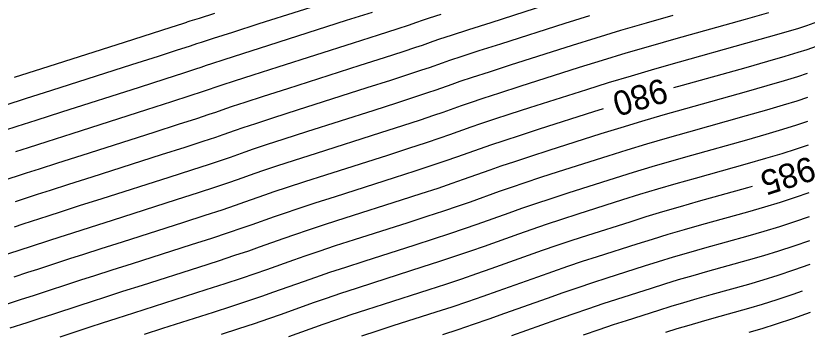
# Model space of a CAD drawing. Extents: x 2175772 to 2185556, y 721391 to 722853.
# Drawn here: x 2178980.9 to 2179071.3, y 721931.4 to 721967.6 of the extents above; entities that cross this region are included whole.
import ezdxf

# ---------------------------------------------------------------- set-up
doc = ezdxf.new("R2010")
doc.units = 0
doc.layers.add('DT_X_Contour_Major', color=7, linetype='Continuous')
doc.layers.add('DT_X_Contour_Minor', color=7, linetype='Continuous')

msp = doc.modelspace()

# ---------------------------------------------------------------- linework, layer by layer
at = {"layer": 'DT_X_Contour_Major'}
for points in [[(2178980.023, 721948.963), (2178981.318, 721949.388), (2178982.129, 721949.65), (2178983.591, 721950.121), (2178985.704, 721950.798), (2178988.467, 721951.683), (2178996.705, 721954.318), (2178999.462, 721955.202), (2179001.555, 721955.878), (2179002.983, 721956.345), (2179003.746, 721956.603), (2179004.897, 721957.015), (2179005.662, 721957.274), (2179007.096, 721957.743), (2179009.198, 721958.421), (2179011.969, 721959.309), (2179020.249, 721961.956), (2179023.022, 721962.845), (2179025.132, 721963.526), (2179026.578, 721964), (2179027.362, 721964.265), (2179028.566, 721964.696), (2179029.32, 721964.952), (2179030.678, 721965.397), (2179032.64, 721966.03), (2179035.206, 721966.852), (2179042.853, 721969.296)], [(2179056.073, 721959.398), (2179057.065, 721959.679), (2179064.33, 721961.707), (2179066.809, 721962.406), (2179068.796, 721962.983), (2179070.291, 721963.438), (2179071.294, 721963.77), (2179073.312, 721964.492)], [(2178979.478, 721934.532), (2178981.437, 721935.162), (2178983.034, 721935.679), (2178984.269, 721936.081), (2178987.082, 721937.004), (2178988.319, 721937.408), (2178989.923, 721937.926), (2178991.893, 721938.56), (2178994.229, 721939.308), (2179000.946, 721941.457), (2179003.269, 721942.205), (2179005.202, 721942.836), (2179006.743, 721943.352), (2179007.894, 721943.752), (2179010.441, 721944.663), (2179011.594, 721945.064), (2179013.14, 721945.581), (2179015.08, 721946.215), (2179017.414, 721946.966), (2179024.164, 721949.124), (2179026.506, 721949.878), (2179028.471, 721950.52), (2179030.058, 721951.052), (2179031.268, 721951.473), (2179033.991, 721952.447), (2179035.176, 721952.86), (2179036.691, 721953.369), (2179038.535, 721953.973), (2179040.707, 721954.672), (2179046.941, 721956.664), (2179048.022, 721957.003)], [(2179065.032, 721948.09), (2179064.472, 721947.93), (2179058.855, 721946.362), (2179056.786, 721945.775), (2179054.792, 721945.191), (2179052.873, 721944.61), (2179051.028, 721944.031), (2179046.209, 721942.491), (2179044.429, 721941.915), (2179042.704, 721941.341), (2179041.032, 721940.768), (2179039.415, 721940.198), (2179035.175, 721938.681), (2179033.539, 721938.105), (2179031.811, 721937.515), (2179029.991, 721936.91), (2179028.079, 721936.291), (2179022.859, 721934.622), (2179020.962, 721934.008), (2179019.184, 721933.419), (2179017.525, 721932.853), (2179015.986, 721932.312), (2179012.042, 721930.901)], [(2179070.736, 721936.117), (2179069.671, 721935.743), (2179067.854, 721935.137), (2179066.168, 721934.607), (2179064.614, 721934.153), (2179060.645, 721933.045), (2179059.184, 721932.631), (2179057.775, 721932.218), (2179056.419, 721931.808), (2179055.116, 721931.399)]]:
    msp.add_lwpolyline(points, dxfattribs=at)
at = {"layer": 'DT_X_Contour_Minor'}
for points in [[(2178979.792, 721957.437), (2178981.99, 721958.141), (2178985.011, 721959.107), (2178994.161, 721962.035), (2178997.178, 721963), (2178999.366, 721963.702), (2179000.726, 721964.14), (2179001.258, 721964.314), (2179001.57, 721964.426), (2179002.103, 721964.6), (2179003.47, 721965.04), (2179005.669, 721965.745), (2179008.702, 721966.715), (2179017.899, 721969.656)], [(2178979.653, 721954.548), (2178981.058, 721954.998), (2178983.228, 721955.693), (2178986.163, 721956.633), (2178995.009, 721959.463), (2178997.939, 721960.401), (2179000.096, 721961.094), (2179001.478, 721961.542), (2179002.087, 721961.744), (2179002.679, 721961.955), (2179003.29, 721962.158), (2179004.679, 721962.607), (2179006.846, 721963.304), (2179009.791, 721964.246), (2179018.682, 721967.089), (2179021.628, 721968.032)], [(2178979.966, 721940.39), (2178981.506, 721940.887), (2178982.571, 721941.234), (2178984.776, 721941.958), (2178985.843, 721942.305), (2178987.39, 721942.804), (2178989.417, 721943.455), (2178991.924, 721944.258), (2178999.25, 721946.601), (2179001.747, 721947.404), (2179003.743, 721948.053), (2179005.239, 721948.549), (2179006.235, 721948.893), (2179008.223, 721949.604), (2179009.221, 721949.948), (2179010.722, 721950.445), (2179012.727, 721951.097), (2179015.236, 721951.903), (2179022.598, 721954.257), (2179025.113, 721955.065), (2179027.135, 721955.723), (2179028.666, 721956.231), (2179029.706, 721956.59), (2179031.821, 721957.347), (2179032.834, 721957.697), (2179034.286, 721958.18), (2179036.177, 721958.796), (2179038.507, 721959.544), (2179045.306, 721961.717), (2179047.908, 721962.533), (2179050.616, 721963.354), (2179053.43, 721964.178), (2179056.349, 721965.005), (2179064.274, 721967.218), (2179066.937, 721967.966)], [(2178980.752, 721960.589), (2178983.858, 721961.582), (2178993.313, 721964.607), (2178998.637, 721966.311), (2178999.974, 721966.739), (2179000.428, 721966.884), (2179000.461, 721966.896), (2179000.821, 721967.011), (2179001.877, 721967.349), (2179003.629, 721967.91)], [(2178980.701, 721937.776), (2178982.27, 721938.283), (2178983.42, 721938.658), (2178985.929, 721939.481), (2178987.081, 721939.856), (2178988.657, 721940.365), (2178990.655, 721941.007), (2178993.077, 721941.783), (2179000.098, 721944.029), (2179002.508, 721944.804), (2179004.472, 721945.445), (2179005.991, 721945.951), (2179007.065, 721946.322), (2179009.332, 721947.134), (2179010.407, 721947.506), (2179011.931, 721948.013), (2179013.904, 721948.656), (2179016.325, 721949.434), (2179023.381, 721951.69), (2179025.809, 721952.471), (2179027.803, 721953.122), (2179029.362, 721953.642), (2179030.487, 721954.031), (2179032.906, 721954.897), (2179034.005, 721955.279), (2179035.488, 721955.774), (2179037.356, 721956.384), (2179039.607, 721957.108), (2179046.123, 721959.19), (2179048.617, 721959.973), (2179051.213, 721960.759), (2179053.909, 721961.549), (2179056.707, 721962.342), (2179064.302, 721964.462), (2179066.873, 721965.186), (2179068.89, 721965.768), (2179070.352, 721966.207), (2179071.261, 721966.504), (2179072.944, 721967.107)], [(2178980.742, 721943.492), (2178981.722, 721943.81), (2178983.623, 721944.434), (2178984.605, 721944.753), (2178986.124, 721945.243), (2178988.179, 721945.903), (2178990.772, 721946.733), (2178998.402, 721949.174), (2179000.985, 721950.003), (2179003.014, 721950.661), (2179004.487, 721951.148), (2179005.405, 721951.463), (2179007.114, 721952.074), (2179008.035, 721952.39), (2179009.514, 721952.878), (2179011.551, 721953.538), (2179014.147, 721954.372), (2179021.815, 721956.823), (2179024.416, 721957.658), (2179026.468, 721958.324), (2179027.97, 721958.821), (2179028.924, 721959.148), (2179030.736, 721959.797), (2179031.663, 721960.115), (2179033.083, 721960.586), (2179034.998, 721961.207), (2179037.406, 721961.98), (2179044.488, 721964.243), (2179047.199, 721965.094), (2179050.02, 721965.948), (2179052.95, 721966.807), (2179055.991, 721967.669)], [(2178980.872, 721946.386), (2178982.471, 721946.911), (2178983.367, 721947.202), (2178984.857, 721947.682), (2178986.942, 721948.35), (2178989.62, 721949.208), (2178997.553, 721951.746), (2179000.224, 721952.603), (2179002.284, 721953.269), (2179003.735, 721953.746), (2179004.576, 721954.033), (2179006.006, 721954.545), (2179006.848, 721954.832), (2179008.305, 721955.31), (2179010.375, 721955.98), (2179013.058, 721956.84), (2179021.032, 721959.39), (2179023.719, 721960.252), (2179025.8, 721960.925), (2179027.274, 721961.41), (2179028.143, 721961.707), (2179029.651, 721962.246), (2179030.491, 721962.534), (2179031.88, 721962.991), (2179033.819, 721963.619), (2179036.306, 721964.416), (2179043.671, 721966.77), (2179046.49, 721967.654)], [(2178980.891, 721952.099), (2178982.324, 721952.56), (2178984.466, 721953.246), (2178987.315, 721954.158), (2178995.857, 721956.89), (2178998.701, 721957.802), (2179000.825, 721958.486), (2179002.231, 721958.943), (2179002.917, 721959.173), (2179003.788, 721959.485), (2179004.476, 721959.716), (2179005.887, 721960.175), (2179008.022, 721960.862), (2179010.88, 721961.778), (2179019.466, 721964.523), (2179022.325, 721965.439), (2179024.464, 721966.127), (2179025.882, 721966.589), (2179026.58, 721966.824), (2179027.481, 721967.146), (2179028.149, 721967.371), (2179029.475, 721967.802)], [(2178980.243, 721931.927), (2178982.172, 721932.548), (2178983.798, 721933.074), (2178985.118, 721933.505), (2178988.234, 721934.528), (2178989.557, 721934.959), (2178991.19, 721935.487), (2178993.131, 721936.112), (2178995.381, 721936.833), (2179001.794, 721938.885), (2179004.031, 721939.605), (2179005.931, 721940.228), (2179007.496, 721940.754), (2179008.724, 721941.182), (2179011.55, 721942.193), (2179012.78, 721942.622), (2179014.349, 721943.148), (2179016.256, 721943.773), (2179018.503, 721944.497), (2179024.947, 721946.557), (2179027.203, 721947.284), (2179029.139, 721947.919), (2179030.755, 721948.463), (2179032.049, 721948.915), (2179035.075, 721949.997), (2179036.347, 721950.442), (2179037.893, 721950.963), (2179039.713, 721951.561), (2179041.808, 721952.236), (2179047.758, 721954.137), (2179050.036, 721954.852), (2179052.406, 721955.57), (2179054.868, 721956.291), (2179057.423, 721957.015), (2179064.359, 721958.951), (2179066.745, 721959.626), (2179068.701, 721960.198), (2179070.229, 721960.668), (2179071.326, 721961.035)], [(2178985.968, 721930.929), (2178989.387, 721932.051), (2178990.796, 721932.511), (2178992.456, 721933.048), (2178994.369, 721933.664), (2179002.642, 721936.312), (2179004.792, 721937.006), (2179006.661, 721937.62), (2179008.248, 721938.155), (2179009.553, 721938.612), (2179012.659, 721939.723), (2179013.966, 721940.179), (2179015.557, 721940.716), (2179017.433, 721941.332), (2179019.592, 721942.028), (2179025.73, 721943.991), (2179027.9, 721944.691), (2179029.807, 721945.318), (2179031.451, 721945.873), (2179032.831, 721946.356), (2179036.16, 721947.548), (2179037.519, 721948.024), (2179039.096, 721948.557), (2179040.892, 721949.149), (2179042.908, 721949.8), (2179048.576, 721951.611), (2179050.745, 721952.291), (2179053.002, 721952.975), (2179055.348, 721953.662), (2179057.781, 721954.352), (2179064.387, 721956.196), (2179066.681, 721956.846), (2179068.607, 721957.414), (2179070.167, 721957.899), (2179071.359, 721958.301)], [(2178995.607, 721931.217), (2178997.686, 721931.883), (2179003.49, 721933.74), (2179005.554, 721934.406), (2179007.39, 721935.012), (2179009, 721935.557), (2179010.383, 721936.041), (2179013.768, 721937.253), (2179015.152, 721937.737), (2179016.766, 721938.284), (2179018.609, 721938.891), (2179020.681, 721939.56), (2179026.513, 721941.424), (2179028.597, 721942.097), (2179030.475, 721942.717), (2179032.147, 721943.284), (2179033.612, 721943.798), (2179037.245, 721945.098), (2179038.69, 721945.605), (2179040.298, 721946.152), (2179042.071, 721946.738), (2179044.009, 721947.363), (2179049.393, 721949.084), (2179051.454, 721949.731), (2179053.599, 721950.381), (2179055.827, 721951.033), (2179058.139, 721951.689), (2179064.415, 721953.441), (2179066.617, 721954.066), (2179068.513, 721954.629), (2179070.105, 721955.129), (2179071.392, 721955.567)], [(2179071.424, 721952.833), (2179070.043, 721952.36), (2179068.419, 721951.845), (2179066.552, 721951.286), (2179064.444, 721950.685), (2179058.497, 721949.025), (2179056.307, 721948.404), (2179054.196, 721947.786), (2179052.164, 721947.17), (2179050.211, 721946.558), (2179045.109, 721944.927), (2179043.25, 721944.326), (2179041.501, 721943.746), (2179039.861, 721943.187), (2179038.33, 721942.648), (2179034.393, 721941.239), (2179032.843, 721940.694), (2179031.143, 721940.116), (2179029.294, 721939.504), (2179027.296, 721938.858), (2179021.77, 721937.091), (2179019.785, 721936.45), (2179017.975, 721935.851), (2179016.339, 721935.295), (2179014.877, 721934.782), (2179011.212, 721933.471), (2179009.752, 721932.958), (2179008.12, 721932.404), (2179006.315, 721931.807), (2179004.338, 721931.168)], [(2179071.49, 721947.364), (2179069.919, 721946.821), (2179068.23, 721946.275), (2179066.424, 721945.726), (2179064.5, 721945.175), (2179059.213, 721943.699), (2179057.266, 721943.147), (2179055.389, 721942.597), (2179053.582, 721942.05), (2179051.846, 721941.505), (2179047.31, 721940.055), (2179045.608, 721939.503), (2179043.906, 721938.935), (2179042.203, 721938.35), (2179040.5, 721937.749), (2179035.956, 721936.123), (2179034.235, 721935.516), (2179032.479, 721934.913), (2179030.688, 721934.317), (2179028.862, 721933.725), (2179023.948, 721932.154), (2179022.138, 721931.567), (2179020.392, 721930.986)], [(2179071.522, 721944.63), (2179069.857, 721944.052), (2179068.136, 721943.491), (2179066.36, 721942.947), (2179064.529, 721942.419), (2179059.571, 721941.035), (2179057.745, 721940.518), (2179055.985, 721940.002), (2179054.291, 721939.489), (2179052.663, 721938.978), (2179048.41, 721937.619), (2179046.787, 721937.092), (2179045.109, 721936.529), (2179043.375, 721935.932), (2179041.585, 721935.299), (2179036.737, 721933.564), (2179034.931, 721932.926), (2179033.146, 721932.312), (2179031.385, 721931.723), (2179029.646, 721931.158)], [(2179071.555, 721941.895), (2179069.795, 721941.282), (2179068.042, 721940.706), (2179066.296, 721940.167), (2179064.557, 721939.664), (2179059.929, 721938.372), (2179058.225, 721937.889), (2179056.582, 721937.408), (2179055, 721936.929), (2179053.481, 721936.452), (2179049.51, 721935.183), (2179047.966, 721934.68), (2179046.311, 721934.124), (2179044.546, 721933.513), (2179042.669, 721932.849), (2179037.518, 721931.006)], [(2179071.588, 721939.161), (2179069.733, 721938.513), (2179067.948, 721937.921), (2179066.232, 721937.387), (2179064.585, 721936.908), (2179060.287, 721935.709), (2179058.704, 721935.26), (2179057.178, 721934.813), (2179055.71, 721934.368), (2179054.298, 721933.925), (2179050.611, 721932.747), (2179049.145, 721932.269), (2179047.514, 721931.718), (2179045.717, 721931.095)], [(2179071.653, 721933.692), (2179069.609, 721932.974), (2179067.759, 721932.352), (2179066.104, 721931.827), (2179064.642, 721931.398)]]:
    msp.add_lwpolyline(points, dxfattribs=at)

# ---------------------------------------------------------------- texts
at = {"layer": 'DT_X_Contour_Major'}
for s, rotation, p in [('980', 196.5632, (2179054.83, 721960.522)), ('985', 197.82025, (2179071.681, 721951.609))]:
    msp.add_text(s, height=2.8, rotation=rotation, dxfattribs=at).set_placement(p)

doc.saveas('drawing.dxf')
